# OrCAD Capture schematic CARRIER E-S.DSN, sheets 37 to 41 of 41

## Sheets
37 B5B7: size A4; block Drivers IGBT/Red fase R
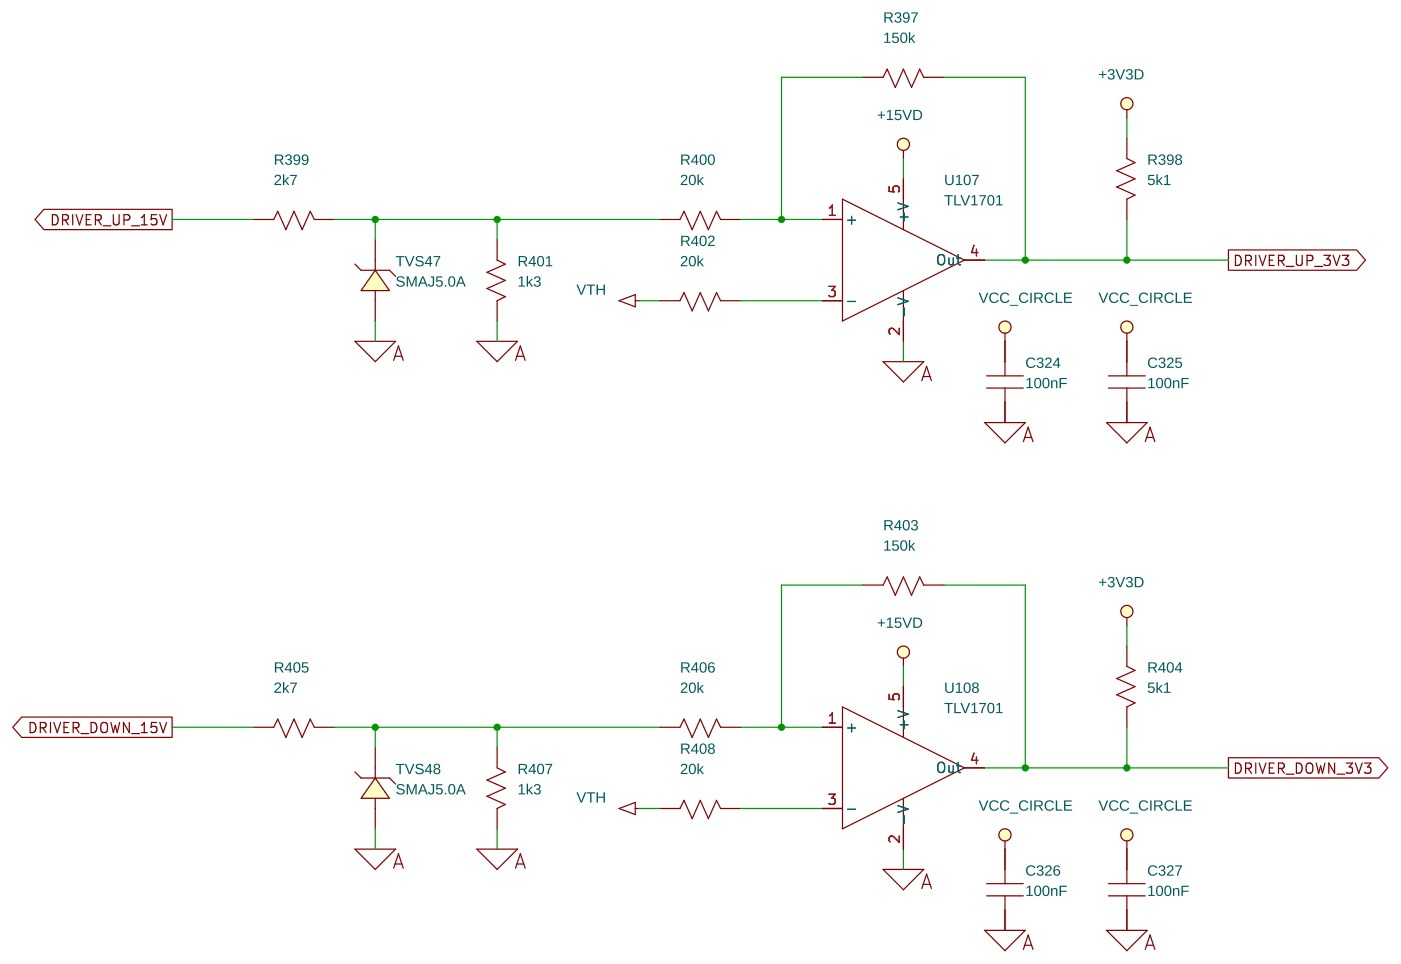
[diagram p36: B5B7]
38 B5B3: size A4; block Drivers IGBT/Generador fase R
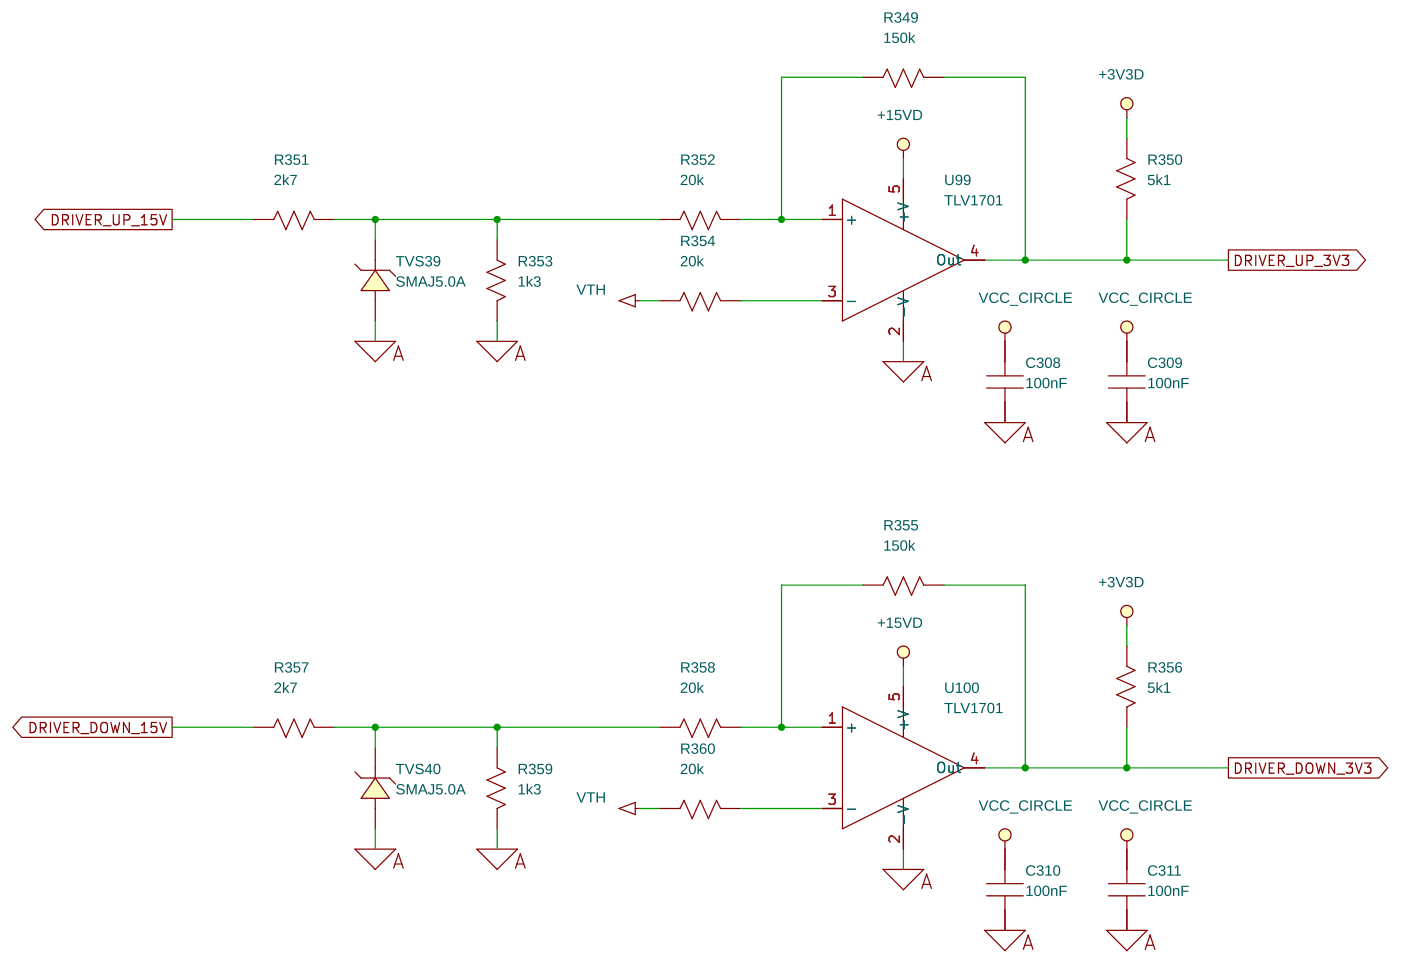
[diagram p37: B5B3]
39 ECP3
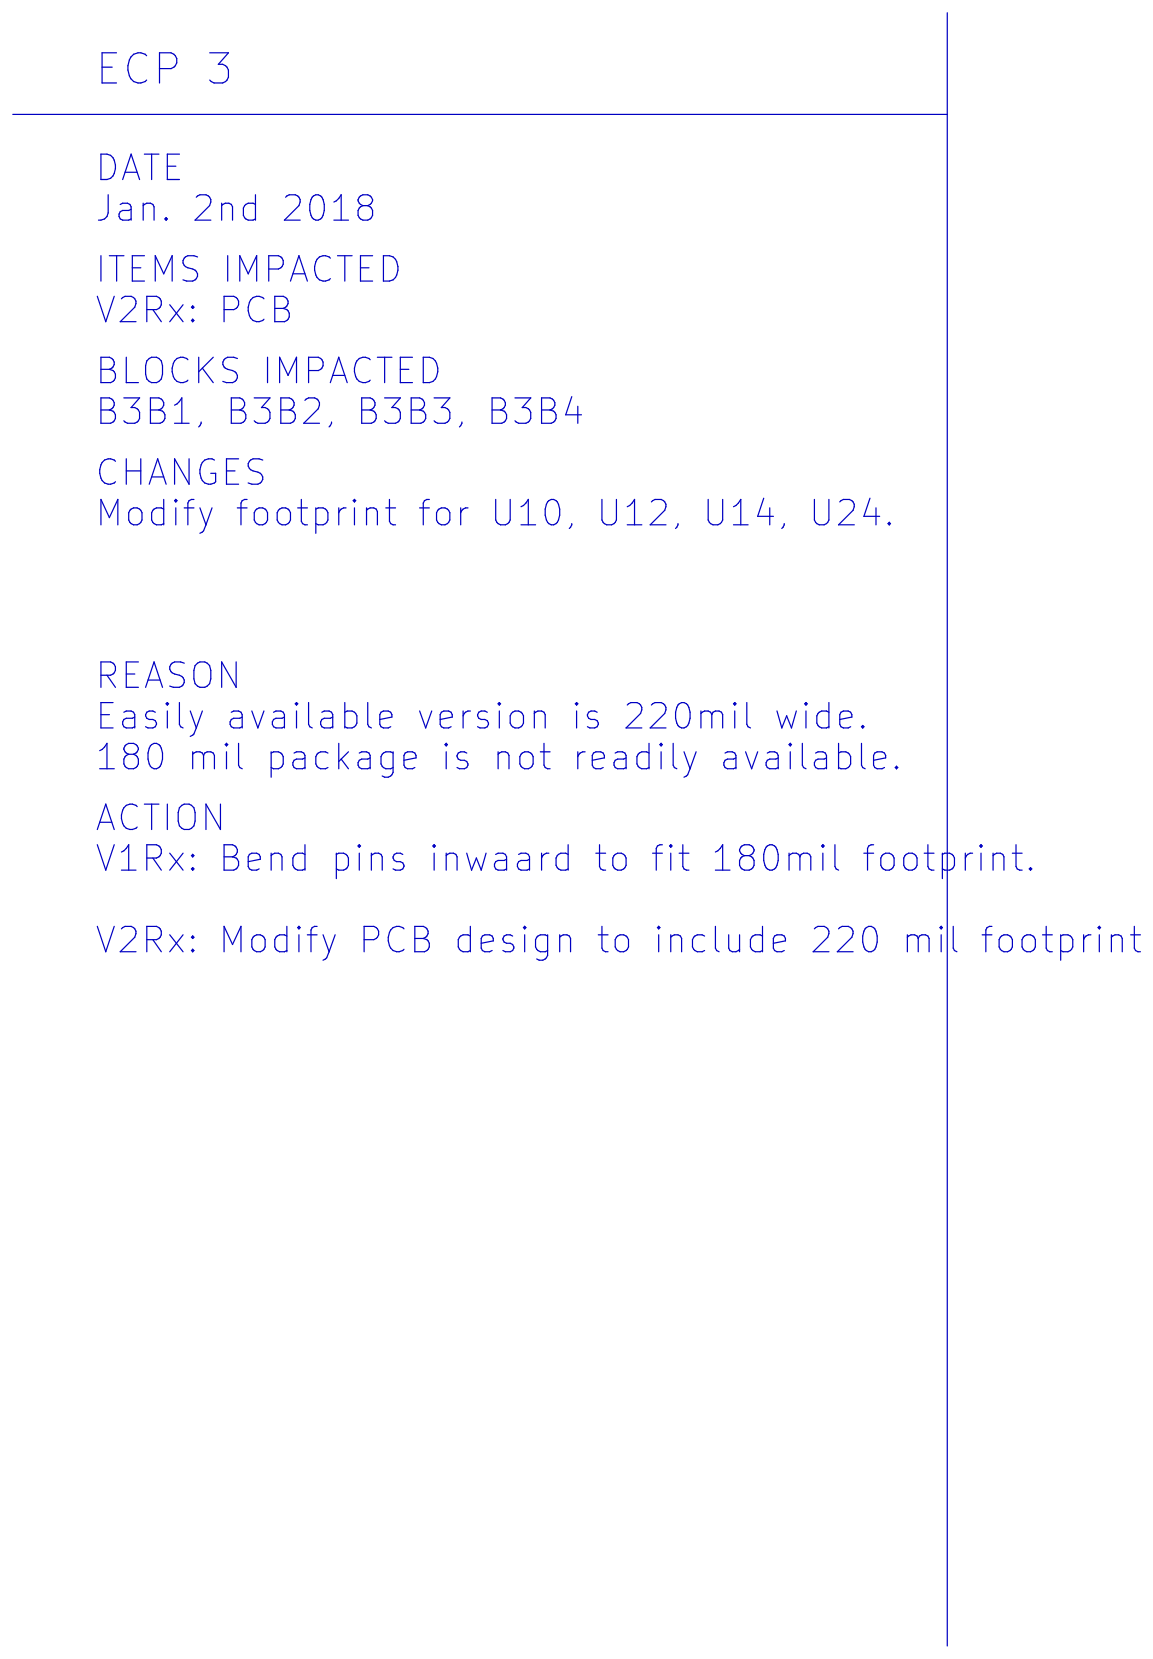
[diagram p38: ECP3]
40 ECP2
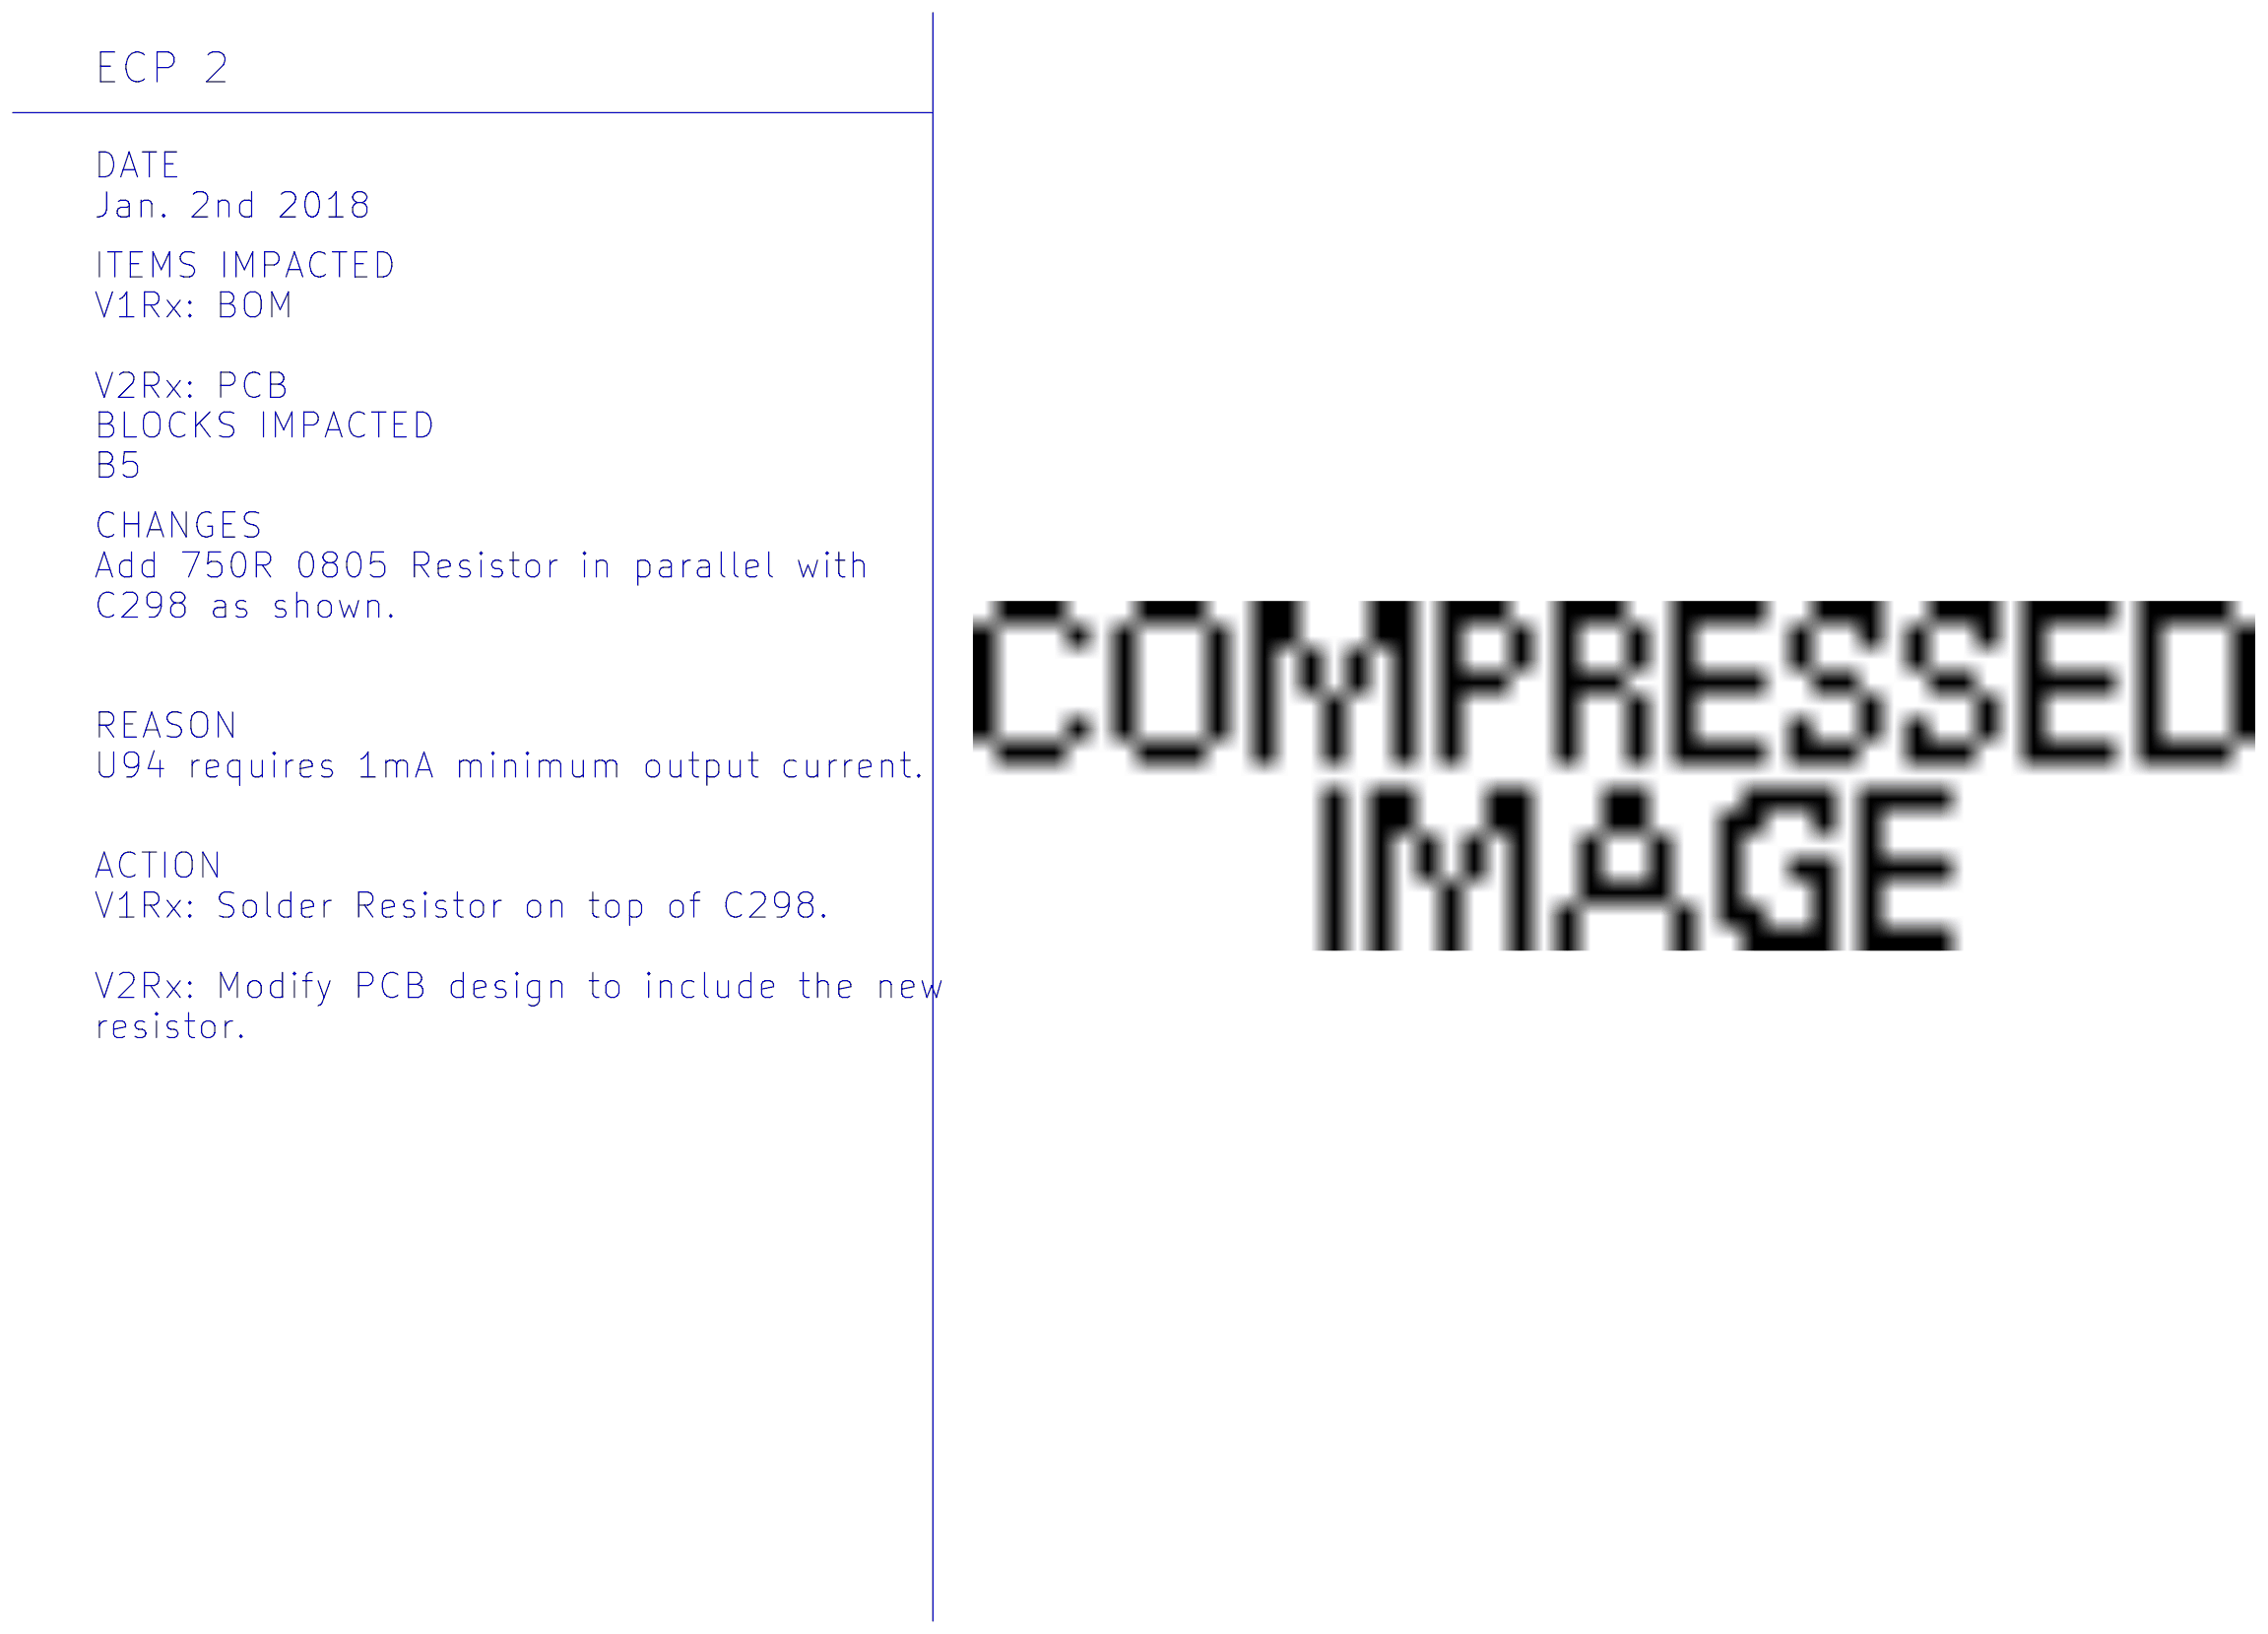
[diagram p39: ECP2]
41 ECP1
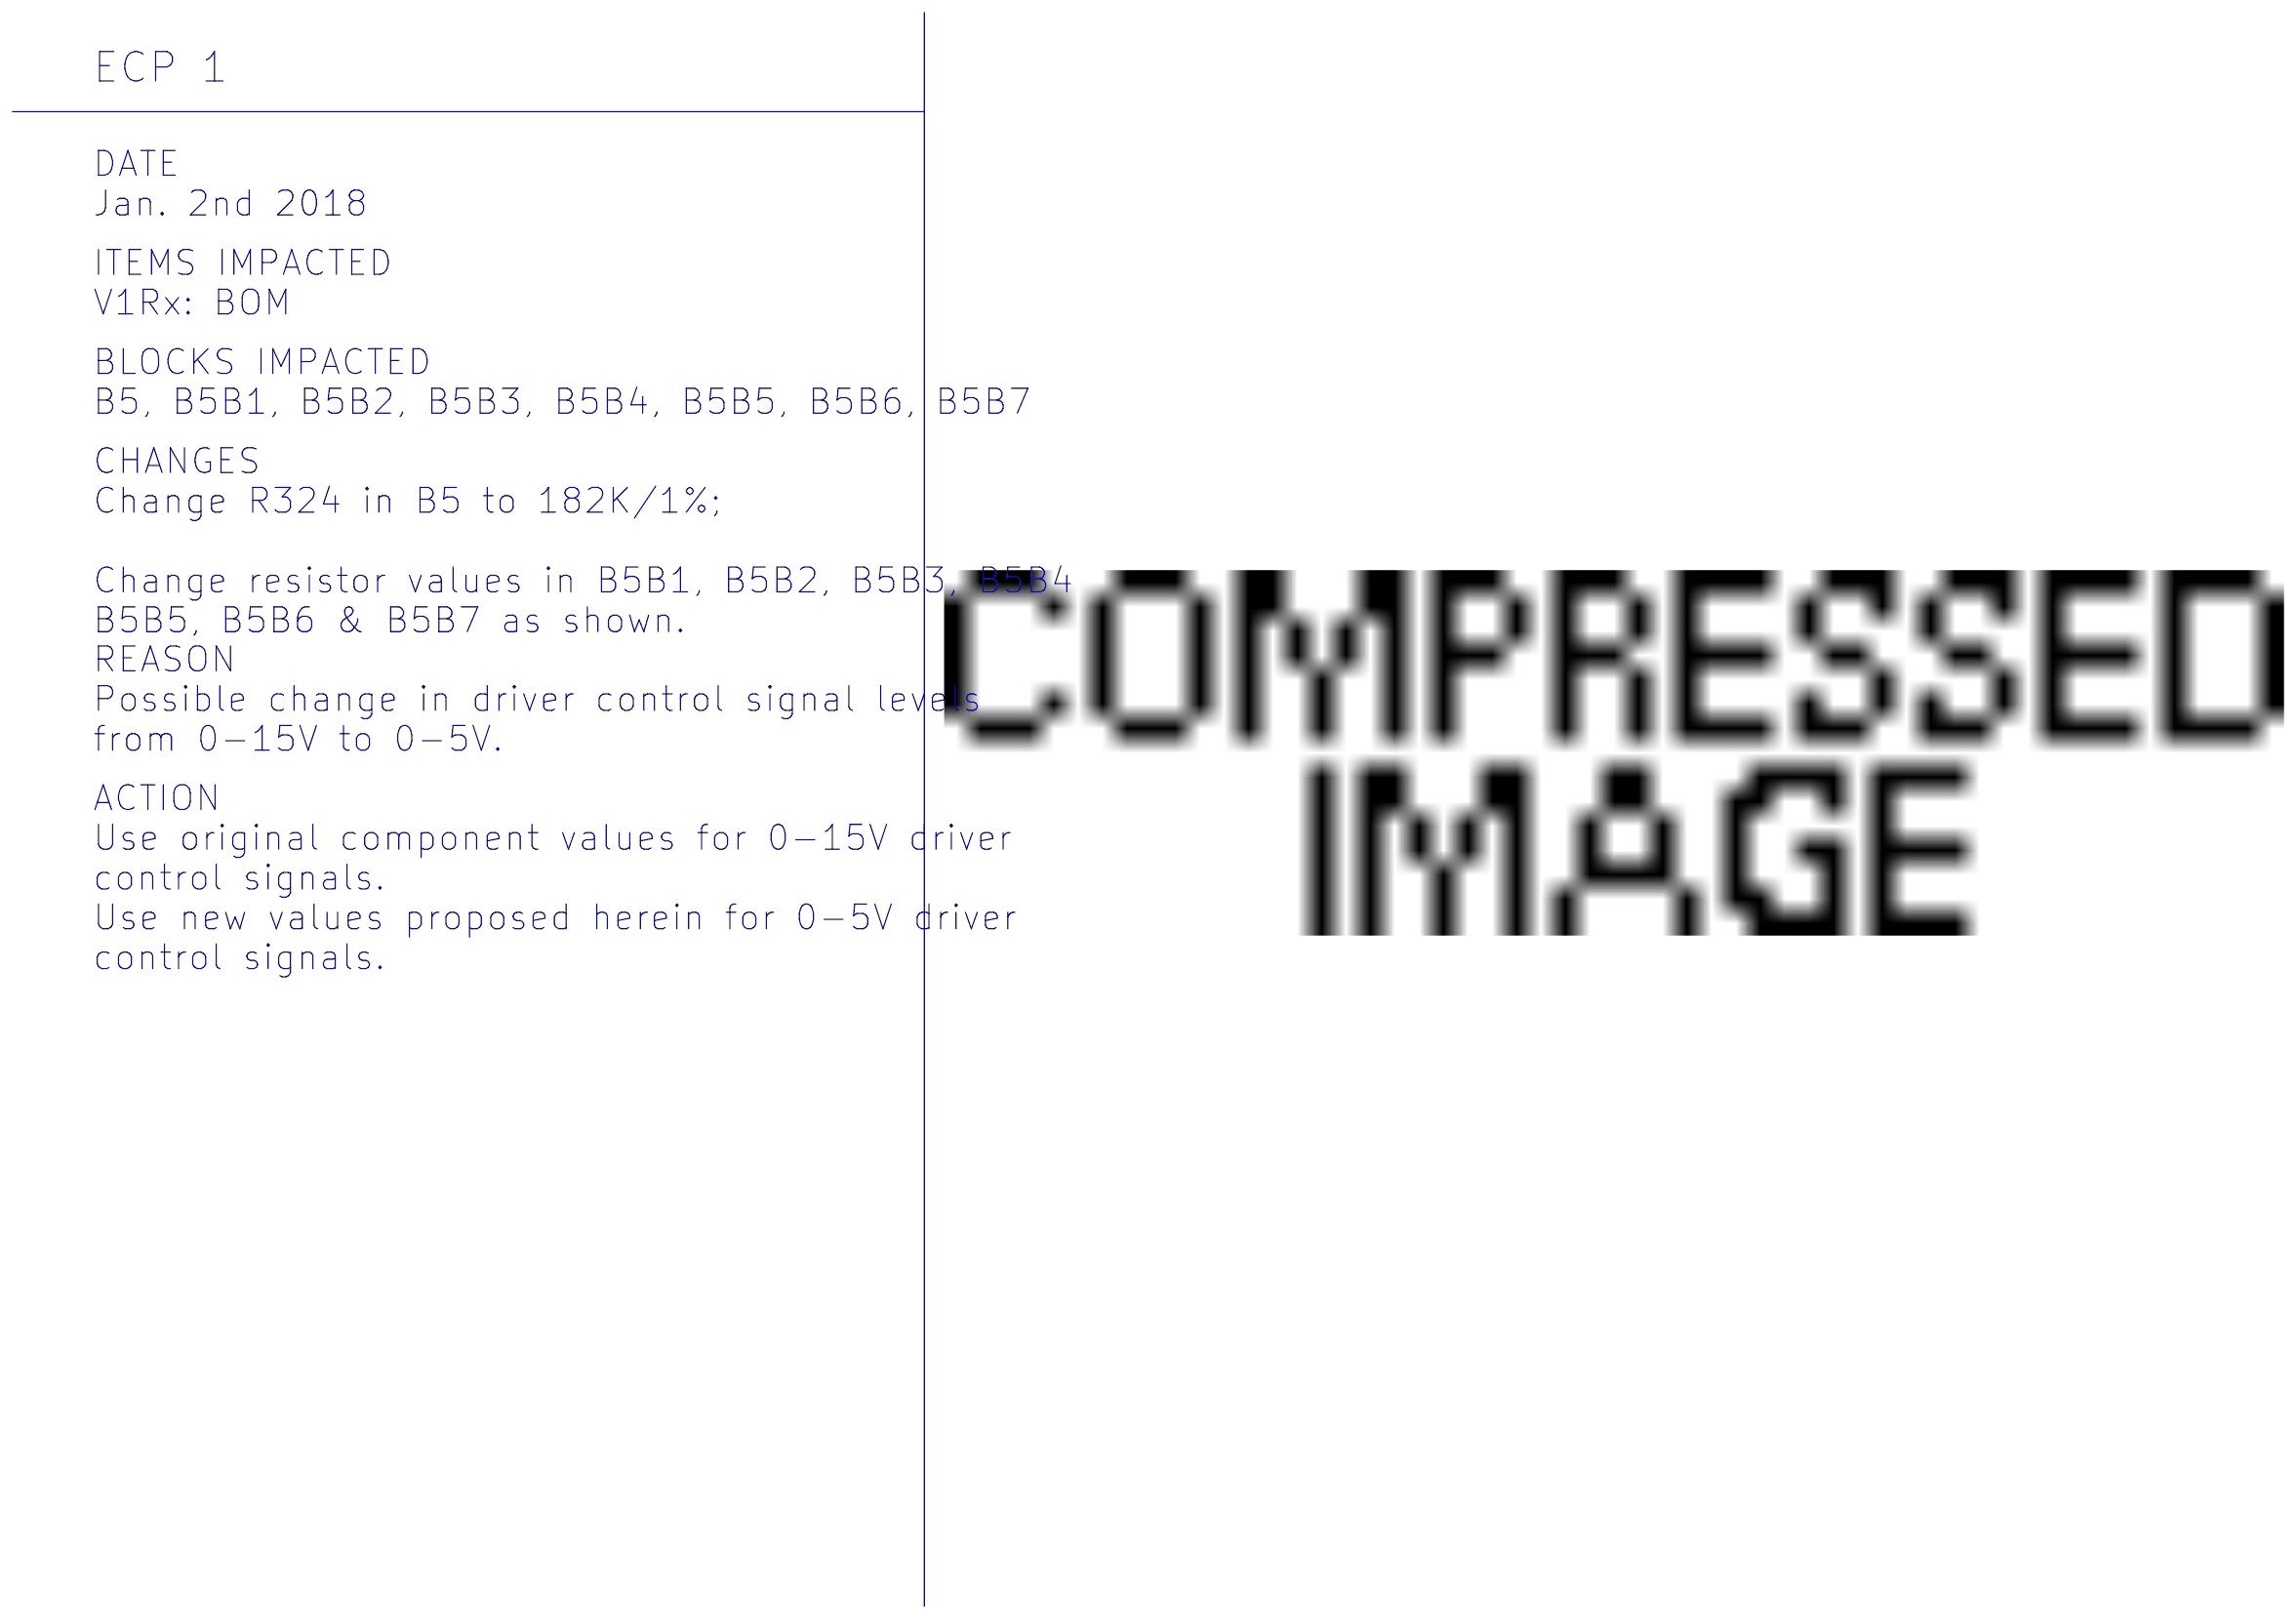
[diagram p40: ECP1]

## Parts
sheet B5B3
C308  100nF  [C/SM/0805/IPC-7351 (2005)/NORMAL]
C309  100nF  [C/SM/0805/IPC-7351 (2005)/NORMAL]
C310  100nF  [C/SM/0805/IPC-7351 (2005)/NORMAL]
C311  100nF  [C/SM/0805/IPC-7351 (2005)/NORMAL]
R349  150k  [R/SM/0805/IPC-7351 (2005)/NORMAL]
R350  5k1  [R/SM/0805/IPC-7351 (2005)/NORMAL]
R351  2k7  [R/SM/0805/IPC-7351 (2005)/NORMAL]
R352  20k  [R/SM/0805/IPC-7351 (2005)/NORMAL]
R353  1k3  [R/SM/0805/IPC-7351 (2005)/NORMAL]
R354  20k  [R/SM/0805/IPC-7351 (2005)/NORMAL]
R355  150k  [R/SM/0805/IPC-7351 (2005)/NORMAL]
R356  5k1  [R/SM/0805/IPC-7351 (2005)/NORMAL]
R357  2k7  [R/SM/0805/IPC-7351 (2005)/NORMAL]
R358  20k  [R/SM/0805/IPC-7351 (2005)/NORMAL]
R359  1k3  [R/SM/0805/IPC-7351 (2005)/NORMAL]
R360  20k  [R/SM/0805/IPC-7351 (2005)/NORMAL]
TVS39  SMAJ5.0A  [SM/DO214AC/IPC-7351 (2005)/NORMAL]
TVS40  SMAJ5.0A  [SM/DO214AC/IPC-7351 (2005)/NORMAL]
U99  TLV1701  [SM/SOT23/5/IPC-7351 (2005)/NORMAL]
U100  TLV1701  [SM/SOT23/5/IPC-7351 (2005)/NORMAL]
sheet B5B7
C324  100nF  [C/SM/0805/IPC-7351 (2005)/NORMAL]
C325  100nF  [C/SM/0805/IPC-7351 (2005)/NORMAL]
C326  100nF  [C/SM/0805/IPC-7351 (2005)/NORMAL]
C327  100nF  [C/SM/0805/IPC-7351 (2005)/NORMAL]
R397  150k  [R/SM/0805/IPC-7351 (2005)/NORMAL]
R398  5k1  [R/SM/0805/IPC-7351 (2005)/NORMAL]
R399  2k7  [R/SM/0805/IPC-7351 (2005)/NORMAL]
R400  20k  [R/SM/0805/IPC-7351 (2005)/NORMAL]
R401  1k3  [R/SM/0805/IPC-7351 (2005)/NORMAL]
R402  20k  [R/SM/0805/IPC-7351 (2005)/NORMAL]
R403  150k  [R/SM/0805/IPC-7351 (2005)/NORMAL]
R404  5k1  [R/SM/0805/IPC-7351 (2005)/NORMAL]
R405  2k7  [R/SM/0805/IPC-7351 (2005)/NORMAL]
R406  20k  [R/SM/0805/IPC-7351 (2005)/NORMAL]
R407  1k3  [R/SM/0805/IPC-7351 (2005)/NORMAL]
R408  20k  [R/SM/0805/IPC-7351 (2005)/NORMAL]
TVS47  SMAJ5.0A  [SM/DO214AC/IPC-7351 (2005)/NORMAL]
TVS48  SMAJ5.0A  [SM/DO214AC/IPC-7351 (2005)/NORMAL]
U107  TLV1701  [SM/SOT23/5/IPC-7351 (2005)/NORMAL]
U108  TLV1701  [SM/SOT23/5/IPC-7351 (2005)/NORMAL]

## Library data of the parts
C308-C311 C324-C327 = CAP_NP: RS: 723-5058
R349-R360 R397-R408 = R
TVS39 TVS40 TVS47 TVS48 = DIODE_ZENER_1: RS: 764-5565
U99 U100 U107 U108 = TLV1701: MFR. P/N: TLV1701AIDBV; RS: 900-9879

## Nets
+3V3D: C309.2 C311.2 C325.2 C327.2 R350.2 R356.2 R398.2 R404.2 ; also on sheet 25 26 27 28 29 30 32 33 34 35 36
+15Vd: C308.2 C310.2 C324.2 C326.2 U99.5(+V) U100.5(+V) U107.5(+V) U108.5(+V) ; also on sheet 31 32 33 34 35 36
GND_ANALOG: C308.1 C309.1 C310.1 C311.1 C324.1 C325.1 C326.1 C327.1 R353.1 R359.1 R401.1 R407.1 TVS39.2(ANODE) TVS40.2(ANODE) TVS47.2(ANODE) TVS48.2(ANODE) U99.2(-V) U100.2(-V) U107.2(-V) U108.2(-V) ; also on sheet 2 3 4 5 6 7 8 9 10 11 12 13 14 15 16 17 18 19 20 21 22 24 25 26 31 32 33 34 35 36
Vth: R354.2 R360.2 R402.2 R408.2 ; also on sheet 31 32 33 34 35 36
Drivers IGBT/Generador fase R/N35234: R351.1 R352.2 R353.2 TVS39.1(CATHODE)
Drivers IGBT/Generador fase R/N35238: R349.2 R352.1 U99.1(+)
Drivers IGBT/Generador fase R/N35342: R354.1 U99.3(-)
Drivers IGBT/Generador fase R/N35592: R357.1 R358.2 R359.2 TVS40.1(CATHODE)
Drivers IGBT/Generador fase R/N35612: R355.2 R358.1 U100.1(+)
Drivers IGBT/Generador fase R/N35696: R360.1 U100.3(-)
Drivers IGBT/N34883: R351.2 ; also on sheet 31
Drivers IGBT/N34887: R357.2 ; also on sheet 31
Drivers IGBT/N35353: R399.2 ; also on sheet 31
Drivers IGBT/N35357: R405.2 ; also on sheet 31
Drivers IGBT/Red fase R/N35234: R399.1 R400.2 R401.2 TVS47.1(CATHODE)
Drivers IGBT/Red fase R/N35238: R397.2 R400.1 U107.1(+)
Drivers IGBT/Red fase R/N35342: R402.1 U107.3(-)
Drivers IGBT/Red fase R/N35592: R405.1 R406.2 R407.2 TVS48.1(CATHODE)
Drivers IGBT/Red fase R/N35612: R403.2 R406.1 U108.1(+)
Drivers IGBT/Red fase R/N35696: R408.1 U108.3(-)
N09599: R349.1 R350.1 U99.4(Out) ; also on sheet 26
N09603: R355.1 R356.1 U100.4(Out) ; also on sheet 26
N09695: R397.1 R398.1 U107.4(Out) ; also on sheet 26
N09699: R403.1 R404.1 U108.4(Out) ; also on sheet 26

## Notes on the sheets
sheet 39
- ECP 3
- DATE
- Jan. 2nd 2018
- ITEMS IMPACTED
- V2Rx: PCB
- BLOCKS IMPACTED
- B3B1, B3B2, B3B3, B3B4
- CHANGES
- Modify footprint for U10, U12, U14, U24.
- REASON
- Easily available version is 220mil wide.
  180 mil package is not readily available.
- ACTION
- V1Rx: Bend pins inwaard to fit 180mil footprint.
  V2Rx: Modify PCB design to include 220 mil footprint
sheet 40
- ECP 2
- DATE
- Jan. 2nd 2018
- ITEMS IMPACTED
- V1Rx: BOM
  V2Rx: PCB
- BLOCKS IMPACTED
- B5
- CHANGES
- Add 750R 0805 Resistor in parallel with
  C298 as shown.
- REASON
- U94 requires 1mA minimum output current.
- ACTION
- V1Rx: Solder Resistor on top of C298.
  V2Rx: Modify PCB design to include the new
  resistor.
sheet 41
- ECP 1
- DATE
- Jan. 2nd 2018
- ITEMS IMPACTED
- V1Rx: BOM
- BLOCKS IMPACTED
- B5, B5B1, B5B2, B5B3, B5B4, B5B5, B5B6, B5B7
- CHANGES
- Change R324 in B5 to 182K/1%;
  Change resistor values in B5B1, B5B2, B5B3, B5B4
  B5B5, B5B6 & B5B7 as shown.
- REASON
- Possible change in driver control signal levels
  from 0-15V to 0-5V.
- ACTION
- Use original component values for 0-15V driver
  control signals.
  Use new values proposed herein for 0-5V driver
  control signals.
